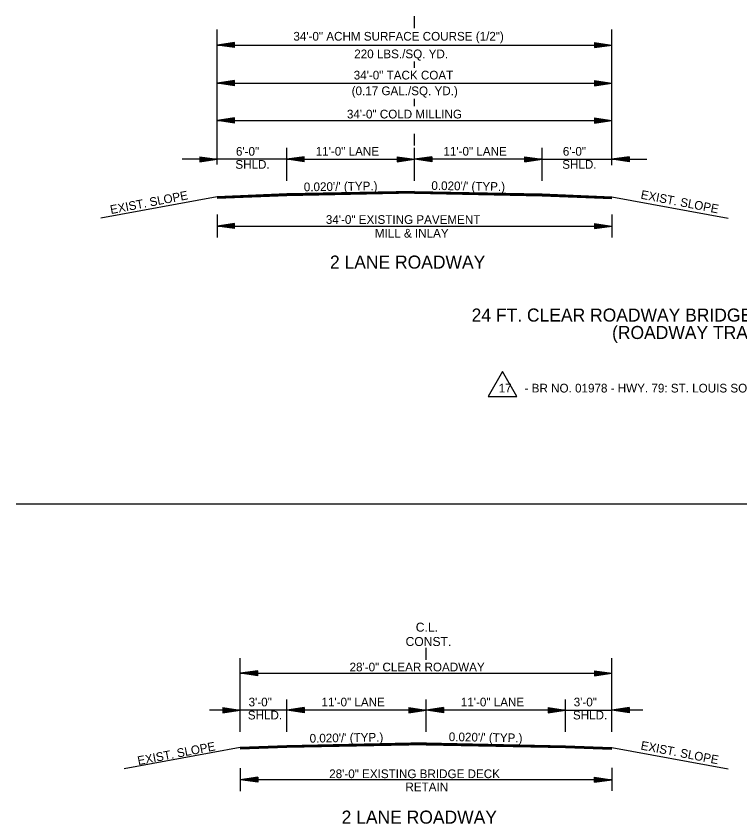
# Model space of a CAD drawing. Extents: x 549600 to 1930787, y -1955432 to 596640.
# Drawn here: x 551009 to 551632, y -1954032 to -1953336 of the extents above; entities that cross this region are included whole.
import ezdxf

# ---------------------------------------------------------------- set-up
doc = ezdxf.new("R2010")
doc.units = 0
doc.layers.add('R_Border', color=7, linetype='Continuous')
doc.layers.add('S_AREA_CALC', color=7, linetype='Continuous')

msp = doc.modelspace()

# ---------------------------------------------------------------- linework, layer by layer
at = {"layer": 'R_Border'}
for p, q in [((551242.02, -1953489.13), (551182.02, -1953491.53)), ((551242.02, -1953489.43), (551182.02, -1953491.83)), ((551242.02, -1953489.73), (551182.02, -1953492.13)), ((551462.02, -1953489.13), (551522.02, -1953491.53)), ((551462.02, -1953489.43), (551522.02, -1953491.83)), ((551462.02, -1953489.73), (551522.02, -1953492.13)), ((551242.02, -1953490.03), (551182.02, -1953492.43)), ((551242.02, -1953490.33), (551182.02, -1953492.73)), ((551242.02, -1953490.63), (551182.02, -1953493.03)), ((551242.02, -1953490.8), (551182.02, -1953493.2)), ((551462.02, -1953490.03), (551522.02, -1953492.43)), ((551462.02, -1953490.33), (551522.02, -1953492.73)), ((551462.02, -1953490.63), (551522.02, -1953493.03)), ((551462.02, -1953490.8), (551522.02, -1953493.2)), ((551415.44, -1953663.61), (551440.24, -1953663.61)), ((551008.97, -1953755.99), (552070.24, -1953755.99))]:
    msp.add_line(p, q, dxfattribs=at)
msp.add_lwpolyline([(551440.24, -1953663.61), (551427.84, -1953642.13), (551415.44, -1953663.61)], dxfattribs=at)
at = {"layer": 'S_AREA_CALC'}
for p, q in [((551352.02, -1953346.37), (551352.02, -1953335.99)), ((551182.02, -1953463.85), (551182.02, -1953347.48)), ((551522.02, -1953464.34), (551522.02, -1953347.48)), ((551197.02, -1953358.6), (551182.02, -1953360.85)), ((551182.02, -1953360.85), (551522.02, -1953360.85)), ((551197.02, -1953363.1), (551182.02, -1953360.85)), ((551197.02, -1953358.97), (551184.52, -1953360.85)), ((551197.02, -1953362.72), (551184.52, -1953360.85)), ((551197.02, -1953359.35), (551187.1, -1953360.85)), ((551197.02, -1953362.34), (551187.1, -1953360.85)), ((551197.02, -1953359.73), (551189.6, -1953360.85)), ((551197.02, -1953361.96), (551189.6, -1953360.85)), ((551197.02, -1953360.11), (551192.14, -1953360.85)), ((551197.02, -1953361.57), (551192.14, -1953360.85)), ((551197.02, -1953360.49), (551194.65, -1953360.85)), ((551197.02, -1953361.2), (551194.65, -1953360.85)), ((551197.02, -1953363.1), (551197.02, -1953358.6)), ((551507.02, -1953358.6), (551522.02, -1953360.85)), ((551507.02, -1953358.6), (551507.02, -1953363.1)), ((551507.02, -1953358.97), (551519.51, -1953360.85)), ((551507.02, -1953359.35), (551516.93, -1953360.85)), ((551507.02, -1953359.73), (551514.44, -1953360.85)), ((551507.02, -1953360.12), (551511.89, -1953360.85)), ((551507.02, -1953360.49), (551509.39, -1953360.85)), ((551507.02, -1953363.1), (551522.02, -1953360.85)), ((551507.02, -1953361.58), (551511.89, -1953360.85)), ((551507.02, -1953362.34), (551516.93, -1953360.85)), ((551507.02, -1953362.72), (551519.51, -1953360.85)), ((551507.02, -1953361.96), (551514.44, -1953360.85)), ((551507.02, -1953361.2), (551509.39, -1953360.85)), ((551352.02, -1953380.59), (551352.02, -1953375.05)), ((551197.02, -1953391.56), (551182.02, -1953393.81)), ((551197.02, -1953391.94), (551184.52, -1953393.81)), ((551197.02, -1953392.32), (551187.1, -1953393.81)), ((551197.02, -1953396.06), (551197.02, -1953391.56)), ((551507.02, -1953391.56), (551522.02, -1953393.81)), ((551507.02, -1953391.56), (551507.02, -1953396.06)), ((551507.02, -1953391.94), (551519.51, -1953393.81)), ((551507.02, -1953392.32), (551516.93, -1953393.81)), ((551182.02, -1953393.81), (551522.02, -1953393.81)), ((551197.02, -1953396.06), (551182.02, -1953393.81)), ((551197.02, -1953395.69), (551184.52, -1953393.81)), ((551197.02, -1953395.3), (551187.1, -1953393.81)), ((551197.02, -1953392.69), (551189.6, -1953393.81)), ((551197.02, -1953394.93), (551189.6, -1953393.81)), ((551197.02, -1953393.08), (551192.14, -1953393.81)), ((551197.02, -1953394.54), (551192.14, -1953393.81)), ((551197.02, -1953393.46), (551194.65, -1953393.81)), ((551197.02, -1953394.16), (551194.65, -1953393.81)), ((551507.02, -1953392.69), (551514.44, -1953393.81)), ((551507.02, -1953393.08), (551511.89, -1953393.81)), ((551507.02, -1953393.46), (551509.39, -1953393.81)), ((551507.02, -1953396.06), (551522.02, -1953393.81)), ((551507.02, -1953394.55), (551511.89, -1953393.81)), ((551507.02, -1953395.3), (551516.93, -1953393.81)), ((551507.02, -1953395.69), (551519.51, -1953393.81)), ((551507.02, -1953394.93), (551514.44, -1953393.81)), ((551507.02, -1953394.16), (551509.39, -1953393.81)), ((551352.02, -1953413.55), (551352.02, -1953407.14)), ((551197.02, -1953423.54), (551182.02, -1953425.79)), ((551182.02, -1953425.79), (551522.02, -1953425.79)), ((551197.02, -1953428.04), (551182.02, -1953425.79)), ((551197.02, -1953423.91), (551184.52, -1953425.79)), ((551197.02, -1953427.66), (551184.52, -1953425.79)), ((551197.02, -1953424.29), (551187.1, -1953425.79)), ((551197.02, -1953427.28), (551187.1, -1953425.79)), ((551197.02, -1953424.67), (551189.6, -1953425.79)), ((551197.02, -1953426.9), (551189.6, -1953425.79)), ((551197.02, -1953425.05), (551192.14, -1953425.79)), ((551197.02, -1953426.51), (551192.14, -1953425.79)), ((551197.02, -1953425.43), (551194.65, -1953425.79)), ((551197.02, -1953426.14), (551194.65, -1953425.79)), ((551197.02, -1953428.04), (551197.02, -1953423.54)), ((551507.02, -1953423.54), (551522.02, -1953425.79)), ((551507.02, -1953423.54), (551507.02, -1953428.04)), ((551507.02, -1953423.91), (551519.51, -1953425.79)), ((551507.02, -1953424.29), (551516.93, -1953425.79)), ((551507.02, -1953424.67), (551514.44, -1953425.79)), ((551507.02, -1953425.06), (551511.89, -1953425.79)), ((551507.02, -1953425.43), (551509.39, -1953425.79)), ((551507.02, -1953428.04), (551522.02, -1953425.79)), ((551507.02, -1953426.52), (551511.89, -1953425.79)), ((551507.02, -1953427.28), (551516.93, -1953425.79)), ((551507.02, -1953427.66), (551519.51, -1953425.79)), ((551507.02, -1953426.9), (551514.44, -1953425.79)), ((551507.02, -1953426.14), (551509.39, -1953425.79)), ((551352.02, -1953447.31), (551352.02, -1953437.44)), ((551242.02, -1953477.98), (551242.02, -1953449.43)), ((551352.02, -1953477.98), (551352.02, -1953449.43)), ((551462.02, -1953477.98), (551462.02, -1953449.43)), ((551242.02, -1953459.32), (551152.02, -1953459.32)), ((551167.02, -1953457.07), (551182.02, -1953459.32)), ((551167.02, -1953457.07), (551167.02, -1953461.57)), ((551167.02, -1953457.45), (551179.51, -1953459.32)), ((551167.02, -1953457.83), (551176.93, -1953459.32)), ((551167.02, -1953458.21), (551174.44, -1953459.32)), ((551167.02, -1953458.6), (551171.89, -1953459.32)), ((551167.02, -1953458.97), (551169.39, -1953459.32)), ((551167.02, -1953461.57), (551182.02, -1953459.32)), ((551167.02, -1953460.06), (551171.89, -1953459.32)), ((551167.02, -1953460.82), (551176.93, -1953459.32)), ((551167.02, -1953461.2), (551179.51, -1953459.32)), ((551167.02, -1953460.44), (551174.44, -1953459.32)), ((551167.02, -1953459.68), (551169.39, -1953459.32)), ((551257.02, -1953457.07), (551242.02, -1953459.32)), ((551257.02, -1953461.57), (551242.02, -1953459.32)), ((551242.02, -1953459.32), (551352.02, -1953459.32)), ((551257.02, -1953457.45), (551244.52, -1953459.32)), ((551257.02, -1953461.2), (551244.52, -1953459.32)), ((551257.02, -1953457.83), (551247.1, -1953459.32)), ((551257.02, -1953460.82), (551247.1, -1953459.32)), ((551257.02, -1953458.21), (551249.6, -1953459.32)), ((551257.02, -1953460.44), (551249.6, -1953459.32)), ((551257.02, -1953458.59), (551252.14, -1953459.32)), ((551257.02, -1953460.05), (551252.14, -1953459.32)), ((551257.02, -1953458.97), (551254.65, -1953459.32)), ((551257.02, -1953459.68), (551254.65, -1953459.32)), ((551257.02, -1953461.57), (551257.02, -1953457.07)), ((551337.02, -1953457.07), (551352.02, -1953459.32)), ((551337.02, -1953457.07), (551337.02, -1953461.57)), ((551337.02, -1953457.45), (551349.51, -1953459.32)), ((551337.02, -1953457.83), (551346.93, -1953459.32)), ((551337.02, -1953458.21), (551344.44, -1953459.32)), ((551337.02, -1953458.6), (551341.89, -1953459.32)), ((551337.02, -1953458.97), (551339.39, -1953459.32)), ((551337.02, -1953461.57), (551352.02, -1953459.32)), ((551337.02, -1953460.06), (551341.89, -1953459.32)), ((551337.02, -1953460.82), (551346.93, -1953459.32)), ((551337.02, -1953461.2), (551349.51, -1953459.32)), ((551337.02, -1953460.44), (551344.44, -1953459.32)), ((551337.02, -1953459.68), (551339.39, -1953459.32)), ((551367.02, -1953457.07), (551352.02, -1953459.32)), ((551462.02, -1953459.32), (551352.02, -1953459.32)), ((551367.02, -1953461.57), (551352.02, -1953459.32)), ((551367.02, -1953457.45), (551354.52, -1953459.32)), ((551367.02, -1953461.2), (551354.52, -1953459.32)), ((551367.02, -1953457.83), (551357.1, -1953459.32)), ((551367.02, -1953460.82), (551357.1, -1953459.32)), ((551367.02, -1953458.21), (551359.6, -1953459.32)), ((551367.02, -1953460.44), (551359.6, -1953459.32)), ((551367.02, -1953458.6), (551362.14, -1953459.32)), ((551367.02, -1953460.06), (551362.14, -1953459.32)), ((551367.02, -1953458.97), (551364.65, -1953459.32)), ((551367.02, -1953459.68), (551364.65, -1953459.32)), ((551367.02, -1953457.07), (551367.02, -1953461.57)), ((551447.02, -1953457.07), (551462.02, -1953459.32)), ((551447.02, -1953461.57), (551447.02, -1953457.07)), ((551447.02, -1953457.45), (551459.51, -1953459.32)), ((551447.02, -1953457.83), (551456.93, -1953459.32)), ((551447.02, -1953458.21), (551454.44, -1953459.32)), ((551447.02, -1953458.59), (551451.89, -1953459.32)), ((551447.02, -1953458.97), (551449.39, -1953459.32)), ((551447.02, -1953461.57), (551462.02, -1953459.32)), ((551447.02, -1953460.05), (551451.89, -1953459.32)), ((551447.02, -1953460.82), (551456.93, -1953459.32)), ((551447.02, -1953461.2), (551459.51, -1953459.32)), ((551447.02, -1953460.44), (551454.44, -1953459.32)), ((551447.02, -1953459.68), (551449.39, -1953459.32)), ((551462.02, -1953459.32), (551552.02, -1953459.32)), ((551537.02, -1953457.07), (551522.02, -1953459.32)), ((551537.02, -1953461.57), (551522.02, -1953459.32)), ((551537.02, -1953457.45), (551524.52, -1953459.32)), ((551537.02, -1953461.2), (551524.52, -1953459.32)), ((551537.02, -1953457.83), (551527.1, -1953459.32)), ((551537.02, -1953460.82), (551527.1, -1953459.32)), ((551537.02, -1953458.21), (551529.6, -1953459.32)), ((551537.02, -1953460.44), (551529.6, -1953459.32)), ((551537.02, -1953458.6), (551532.14, -1953459.32)), ((551537.02, -1953460.06), (551532.14, -1953459.32)), ((551537.02, -1953458.97), (551534.65, -1953459.32)), ((551537.02, -1953459.68), (551534.65, -1953459.32)), ((551537.02, -1953457.07), (551537.02, -1953461.57)), ((551352.02, -1953486.93), (551242.02, -1953489.13)), ((551352.05, -1953487.23), (551242.02, -1953489.43)), ((551352.04, -1953487.53), (551242.02, -1953489.73)), ((551352.04, -1953487.83), (551242.02, -1953490.03)), ((551352.04, -1953488.13), (551242.02, -1953490.33)), ((551352.05, -1953488.43), (551242.02, -1953490.63)), ((551352.05, -1953488.6), (551242.02, -1953490.8)), ((551351.98, -1953488.6), (551462.02, -1953490.8)), ((551351.99, -1953488.13), (551462.02, -1953490.33)), ((551351.99, -1953488.43), (551462.02, -1953490.63)), ((551352, -1953487.83), (551462.02, -1953490.03)), ((551352.01, -1953487.23), (551462.02, -1953489.43)), ((551352.01, -1953487.53), (551462.02, -1953489.73)), ((551352.02, -1953486.93), (551462.02, -1953489.13)), ((551182.02, -1953491.53), (551081.95, -1953509.91)), ((551522.02, -1953491.53), (551622.09, -1953509.91)), ((551182.02, -1953506.79), (551182.02, -1953526.79)), ((551522.02, -1953506.79), (551522.02, -1953526.79)), ((551197.02, -1953514.54), (551182.02, -1953516.79)), ((551182.02, -1953516.79), (551522.02, -1953516.79)), ((551197.02, -1953519.04), (551182.02, -1953516.79)), ((551197.02, -1953514.91), (551184.52, -1953516.79)), ((551197.02, -1953518.66), (551184.52, -1953516.79)), ((551197.02, -1953515.3), (551187.1, -1953516.79)), ((551197.02, -1953518.28), (551187.1, -1953516.79)), ((551197.02, -1953515.67), (551189.6, -1953516.79)), ((551197.02, -1953517.91), (551189.6, -1953516.79)), ((551197.02, -1953516.05), (551192.14, -1953516.79)), ((551197.02, -1953517.52), (551192.14, -1953516.79)), ((551197.02, -1953516.44), (551194.65, -1953516.79)), ((551197.02, -1953517.14), (551194.65, -1953516.79)), ((551197.02, -1953519.04), (551197.02, -1953514.54)), ((551507.02, -1953514.54), (551522.02, -1953516.79)), ((551507.02, -1953514.54), (551507.02, -1953519.04)), ((551507.02, -1953514.91), (551519.51, -1953516.79)), ((551507.02, -1953515.3), (551516.93, -1953516.79)), ((551507.02, -1953515.67), (551514.44, -1953516.79)), ((551507.02, -1953516.06), (551511.89, -1953516.79)), ((551507.02, -1953516.44), (551509.39, -1953516.79)), ((551507.02, -1953519.04), (551522.02, -1953516.79)), ((551507.02, -1953517.52), (551511.89, -1953516.79)), ((551507.02, -1953518.28), (551516.93, -1953516.79)), ((551507.02, -1953518.66), (551519.51, -1953516.79)), ((551507.02, -1953517.91), (551514.44, -1953516.79)), ((551507.02, -1953517.14), (551509.39, -1953516.79)), ((551362.02, -1953890.45), (551362.02, -1953880.08)), ((551202.02, -1953952.55), (551202.02, -1953889.03)), ((551522.02, -1953952.55), (551522.02, -1953889.03)), ((551217.02, -1953899.88), (551202.02, -1953902.13)), ((551217.02, -1953900.25), (551204.52, -1953902.13)), ((551217.02, -1953904.38), (551217.02, -1953899.88)), ((551507.02, -1953899.88), (551522.02, -1953902.13)), ((551507.02, -1953899.88), (551507.02, -1953904.38)), ((551507.02, -1953900.25), (551519.51, -1953902.13)), ((551202.02, -1953902.13), (551522.02, -1953902.13)), ((551217.02, -1953904.38), (551202.02, -1953902.13)), ((551217.02, -1953904), (551204.52, -1953902.13)), ((551217.02, -1953900.64), (551207.1, -1953902.13)), ((551217.02, -1953903.62), (551207.1, -1953902.13)), ((551217.02, -1953901.01), (551209.6, -1953902.13)), ((551217.02, -1953903.25), (551209.6, -1953902.13)), ((551217.02, -1953901.39), (551212.14, -1953902.13)), ((551217.02, -1953902.86), (551212.14, -1953902.13)), ((551217.02, -1953901.78), (551214.65, -1953902.13)), ((551217.02, -1953902.48), (551214.65, -1953902.13)), ((551507.02, -1953900.64), (551516.93, -1953902.13)), ((551507.02, -1953901.01), (551514.44, -1953902.13)), ((551507.02, -1953901.4), (551511.89, -1953902.13)), ((551507.02, -1953901.78), (551509.39, -1953902.13)), ((551507.02, -1953904.38), (551522.02, -1953902.13)), ((551507.02, -1953902.86), (551511.89, -1953902.13)), ((551507.02, -1953903.62), (551516.93, -1953902.13)), ((551507.02, -1953904), (551519.51, -1953902.13)), ((551507.02, -1953903.25), (551514.44, -1953902.13)), ((551507.02, -1953902.48), (551509.39, -1953902.13)), ((551242.02, -1953952.55), (551242.02, -1953924.6)), ((551362.02, -1953952.55), (551362.02, -1953924.6)), ((551482.02, -1953952.55), (551482.02, -1953924.6)), ((551202.02, -1953933.79), (551175.5, -1953933.79)), ((551187.02, -1953931.54), (551202.02, -1953933.79)), ((551187.02, -1953931.54), (551187.02, -1953936.04)), ((551187.02, -1953931.91), (551199.51, -1953933.79)), ((551187.02, -1953932.3), (551196.93, -1953933.79)), ((551187.02, -1953932.67), (551194.44, -1953933.79)), ((551187.02, -1953933.06), (551191.89, -1953933.79)), ((551187.02, -1953933.44), (551189.39, -1953933.79)), ((551187.02, -1953936.04), (551202.02, -1953933.79)), ((551187.02, -1953934.52), (551191.89, -1953933.79)), ((551187.02, -1953935.28), (551196.93, -1953933.79)), ((551187.02, -1953935.66), (551199.51, -1953933.79)), ((551187.02, -1953934.91), (551194.44, -1953933.79)), ((551187.02, -1953934.14), (551189.39, -1953933.79)), ((551242.02, -1953933.79), (551202.02, -1953933.79)), ((551257.02, -1953931.54), (551242.02, -1953933.79)), ((551362.02, -1953933.79), (551242.02, -1953933.79)), ((551257.02, -1953936.04), (551242.02, -1953933.79)), ((551257.02, -1953931.91), (551244.52, -1953933.79)), ((551257.02, -1953935.66), (551244.52, -1953933.79)), ((551257.02, -1953932.3), (551247.1, -1953933.79)), ((551257.02, -1953935.28), (551247.1, -1953933.79)), ((551257.02, -1953932.67), (551249.6, -1953933.79)), ((551257.02, -1953934.91), (551249.6, -1953933.79)), ((551257.02, -1953933.06), (551252.14, -1953933.79)), ((551257.02, -1953934.52), (551252.14, -1953933.79)), ((551257.02, -1953933.44), (551254.65, -1953933.79)), ((551257.02, -1953934.14), (551254.65, -1953933.79)), ((551257.02, -1953931.54), (551257.02, -1953936.04)), ((551347.02, -1953931.54), (551362.02, -1953933.79)), ((551347.02, -1953931.54), (551347.02, -1953936.04)), ((551347.02, -1953931.91), (551359.51, -1953933.79)), ((551347.02, -1953932.3), (551356.93, -1953933.79)), ((551347.02, -1953932.67), (551354.44, -1953933.79)), ((551347.02, -1953933.06), (551351.89, -1953933.79)), ((551347.02, -1953933.44), (551349.39, -1953933.79)), ((551347.02, -1953936.04), (551362.02, -1953933.79)), ((551347.02, -1953934.52), (551351.89, -1953933.79)), ((551347.02, -1953935.28), (551356.93, -1953933.79)), ((551347.02, -1953935.66), (551359.51, -1953933.79)), ((551347.02, -1953934.91), (551354.44, -1953933.79)), ((551347.02, -1953934.14), (551349.39, -1953933.79)), ((551377.02, -1953931.54), (551362.02, -1953933.79)), ((551482.02, -1953933.79), (551362.02, -1953933.79)), ((551377.02, -1953936.04), (551362.02, -1953933.79)), ((551377.02, -1953931.91), (551364.52, -1953933.79)), ((551377.02, -1953935.66), (551364.52, -1953933.79)), ((551377.02, -1953932.3), (551367.1, -1953933.79)), ((551377.02, -1953935.28), (551367.1, -1953933.79)), ((551377.02, -1953932.67), (551369.6, -1953933.79)), ((551377.02, -1953934.91), (551369.6, -1953933.79)), ((551377.02, -1953933.06), (551372.14, -1953933.79)), ((551377.02, -1953934.52), (551372.14, -1953933.79)), ((551377.02, -1953933.44), (551374.65, -1953933.79)), ((551377.02, -1953934.14), (551374.65, -1953933.79)), ((551377.02, -1953931.54), (551377.02, -1953936.04)), ((551467.02, -1953931.54), (551482.02, -1953933.79)), ((551467.02, -1953931.54), (551467.02, -1953936.04)), ((551467.02, -1953931.91), (551479.51, -1953933.79)), ((551467.02, -1953932.3), (551476.93, -1953933.79)), ((551467.02, -1953932.67), (551474.44, -1953933.79)), ((551467.02, -1953933.06), (551471.89, -1953933.79)), ((551467.02, -1953933.44), (551469.39, -1953933.79)), ((551467.02, -1953936.04), (551482.02, -1953933.79)), ((551467.02, -1953934.52), (551471.89, -1953933.79)), ((551467.02, -1953935.28), (551476.93, -1953933.79)), ((551467.02, -1953935.66), (551479.51, -1953933.79)), ((551467.02, -1953934.91), (551474.44, -1953933.79)), ((551467.02, -1953934.14), (551469.39, -1953933.79)), ((551482.02, -1953933.79), (551522.02, -1953933.79)), ((551537.02, -1953931.54), (551522.02, -1953933.79)), ((551537.02, -1953936.04), (551522.02, -1953933.79)), ((551548.54, -1953933.79), (551522.02, -1953933.79)), ((551537.02, -1953931.91), (551524.52, -1953933.79)), ((551537.02, -1953935.66), (551524.52, -1953933.79)), ((551537.02, -1953932.3), (551527.1, -1953933.79)), ((551537.02, -1953935.28), (551527.1, -1953933.79)), ((551537.02, -1953932.67), (551529.6, -1953933.79)), ((551537.02, -1953934.91), (551529.6, -1953933.79)), ((551537.02, -1953933.06), (551532.14, -1953933.79)), ((551537.02, -1953934.52), (551532.14, -1953933.79)), ((551537.02, -1953933.44), (551534.65, -1953933.79)), ((551537.02, -1953934.14), (551534.65, -1953933.79)), ((551537.02, -1953931.54), (551537.02, -1953936.04)), ((551362.02, -1953962.1), (551242.02, -1953964.5)), ((551362.02, -1953962.4), (551242.02, -1953964.8)), ((551362.02, -1953962.7), (551242.02, -1953965.1)), ((551362.02, -1953963), (551242.02, -1953965.4)), ((551362.02, -1953962.1), (551482.02, -1953964.5)), ((551362.02, -1953962.4), (551482.02, -1953964.8)), ((551362.02, -1953962.7), (551482.02, -1953965.1)), ((551362.02, -1953963), (551482.02, -1953965.4)), ((551202.02, -1953966.1), (551101.95, -1953984.48)), ((551242.02, -1953964.5), (551202.02, -1953966.1)), ((551242.02, -1953964.8), (551202.02, -1953966.4)), ((551242.02, -1953965.1), (551202.02, -1953966.7)), ((551242.02, -1953965.4), (551202.02, -1953967)), ((551242.02, -1953965.7), (551202.02, -1953967.3)), ((551242.02, -1953966), (551202.02, -1953967.6)), ((551362.02, -1953963.3), (551242.02, -1953965.7)), ((551362.02, -1953963.6), (551242.02, -1953966)), ((551362.02, -1953963.77), (551242.02, -1953966.17)), ((551362.02, -1953963.3), (551482.02, -1953965.7)), ((551362.02, -1953963.6), (551482.02, -1953966)), ((551362.02, -1953963.77), (551482.02, -1953966.17)), ((551482.02, -1953964.5), (551522.02, -1953966.1)), ((551482.02, -1953964.8), (551522.02, -1953966.4)), ((551482.02, -1953965.1), (551522.02, -1953966.7)), ((551482.02, -1953965.4), (551522.02, -1953967)), ((551482.02, -1953965.7), (551522.02, -1953967.3)), ((551482.02, -1953966), (551522.02, -1953967.6)), ((551522.02, -1953966.1), (551622.09, -1953984.48)), ((551202.02, -1953983.76), (551202.02, -1954003.76)), ((551522.02, -1953983.51), (551522.02, -1954003.51)), ((551217.02, -1953991.51), (551202.02, -1953993.76)), ((551217.02, -1953996.01), (551202.02, -1953993.76)), ((551522.02, -1953993.76), (551202.02, -1953993.76)), ((551217.02, -1953991.88), (551204.52, -1953993.76)), ((551217.02, -1953995.63), (551204.52, -1953993.76)), ((551217.02, -1953992.26), (551207.1, -1953993.76)), ((551217.02, -1953995.25), (551207.1, -1953993.76)), ((551217.02, -1953992.64), (551209.6, -1953993.76)), ((551217.02, -1953994.87), (551209.6, -1953993.76)), ((551217.02, -1953993.03), (551212.14, -1953993.76)), ((551217.02, -1953994.49), (551212.14, -1953993.76)), ((551217.02, -1953993.4), (551214.65, -1953993.76)), ((551217.02, -1953994.11), (551214.65, -1953993.76)), ((551217.02, -1953991.51), (551217.02, -1953996.01)), ((551507.02, -1953991.51), (551522.02, -1953993.76)), ((551507.02, -1953996.01), (551507.02, -1953991.51)), ((551507.02, -1953991.88), (551519.51, -1953993.76)), ((551507.02, -1953992.26), (551516.93, -1953993.76)), ((551507.02, -1953992.64), (551514.44, -1953993.76)), ((551507.02, -1953993.02), (551511.89, -1953993.76)), ((551507.02, -1953993.4), (551509.39, -1953993.76)), ((551507.02, -1953996.01), (551522.02, -1953993.76)), ((551507.02, -1953994.48), (551511.89, -1953993.76)), ((551507.02, -1953995.25), (551516.93, -1953993.76)), ((551507.02, -1953995.63), (551519.51, -1953993.76)), ((551507.02, -1953994.87), (551514.44, -1953993.76)), ((551507.02, -1953994.11), (551509.39, -1953993.76))]:
    msp.add_line(p, q, dxfattribs=at)

# ---------------------------------------------------------------- texts
at = {"layer": 'R_Border'}
for s, height, p in [('2 LANE ROADWAY', 11.25, (551279.24, -1953553.49)), ('24 FT. CLEAR ROADWAY BRIDGE - HYDRODEMOLITION', 11.25, (551401.23, -1953599.12)), ('(ROADWAY TRANSITIONS)', 11.25, (551522.18, -1953614.12)), ('17', 7.5, (551424.48, -1953660.2)), ('- BR NO. 01978 - HWY. 79: ST. LOUIS SOUTHWESTERN RAILROAD BR.', 7.5, (551446.84, -1953660.2))]:
    msp.add_text(s, height=height, dxfattribs=at).set_placement(p)
at = {"layer": 'S_AREA_CALC'}
for s, height, p in [('34\'-0" ACHM SURFACE COURSE (1/2")', 7.5, (551247.73, -1953357.08)), ('220 LBS./SQ. YD. ', 7.5, (551300.14, -1953372.26)), ('34\'-0" TACK COAT', 7.5, (551299.67, -1953390.55)), ('(0.17 GAL./SQ. YD.)', 7.5, (551297.93, -1953404.09)), ('34\'-0" COLD MILLING ', 7.5, (551293.82, -1953424.12)), ('6\'-0"', 7.5, (551198.26, -1953456.22)), ('11\'-0" LANE', 7.5, (551266.96, -1953456.15)), ('11\'-0" LANE', 7.5, (551376.96, -1953456.15)), ('6\'-0"', 7.5, (551479.78, -1953456.22)), ('SHLD.', 7.5, (551197.76, -1953467.47)), ('SHLD.', 7.5, (551479.28, -1953467.47)), ('34\'-0" EXISTING PAVEMENT', 7.5, (551275.69, -1953514.96)), ('MILL & INLAY', 7.5, (551317.88, -1953526.74)), ('C.L.', 7.8, (551353.12, -1953866.26)), ('CONST.', 7.8, (551344.34, -1953878.63)), ('28\'-0" CLEAR ROADWAY', 7.5, (551296.11, -1953900.46)), ('3\'-0"', 7.5, (551209.17, -1953930.62)), ('11\'-0" LANE', 7.5, (551271.96, -1953930.62)), ('11\'-0" LANE', 7.5, (551391.96, -1953930.62)), ('3\'-0"', 7.5, (551489.17, -1953930.62)), ('SHLD.', 7.5, (551208.49, -1953941.87)), ('SHLD.', 7.5, (551488.49, -1953941.87)), ('28\'-0" EXISTING BRIDGE DECK', 7.5, (551278.57, -1953992.43)), ('RETAIN', 7.5, (551344.21, -1954003.71)), ('2 LANE ROADWAY', 11.25, (551289.29, -1954031.65))]:
    msp.add_text(s, height=height, dxfattribs=at).set_placement(p)
for s, rotation, p in [("0.020'/' (TYP.)", 0.87191, (551256.76, -1953486.89)), ("0.020'/' (TYP.)", 359.12809, (551366.5, -1953485.66)), ('EXIST. SLOPE', 10.88286, (551090.66, -1953506.53)), ('EXIST. SLOPE', 349.11714, (551546.4, -1953493.13)), ("0.020'/' (TYP.)", 0.97192, (551261.76, -1953961.89)), ("0.020'/' (TYP.)", 359.02808, (551381.5, -1953960.52)), ('EXIST. SLOPE', 10.88286, (551114.23, -1953981.26)), ('EXIST. SLOPE', 349.11714, (551546.4, -1953967.69))]:
    msp.add_text(s, height=7.5, rotation=rotation, dxfattribs=at).set_placement(p)

doc.saveas('drawing.dxf')
